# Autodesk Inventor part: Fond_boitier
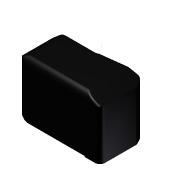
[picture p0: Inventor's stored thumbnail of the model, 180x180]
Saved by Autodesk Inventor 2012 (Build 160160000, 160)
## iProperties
Created: 2011-07
Part Number: Fond_boitier
Document SubType Name: Modeling
Designer: domi
Density: 1 g/cm^3
Material: Par défaut
Author: domi
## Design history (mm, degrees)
sketch "Esquisse1"
  geometry: L1 (-13.986, -11.692)-(16.704, -11.692) reference; L2 (18.504, -9.892)-(18.504, 4.208) reference; L3 (18.352, 4.844)-(17.078, 7.344) reference; L4 (15.831, 8.108)-(12.304, 8.108) reference; L5 (9.472, 9.948)-(7.197, 15.058) reference; L6 (6.731, 15.749)-(4.851, 17.696) reference; L7 (-10.621, 14.519)-(-16.593, 4.961) reference; L8 (16.704, -10.292)-(-13.986, -10.292) reference; L9 (-15.406, 4.219)-(-9.678, 13.386) reference; L10 (4.275, 16.278)-(5.724, 14.777) reference; L11 (5.918, 14.489)-(8.193, 9.378) reference; L12 (12.304, 6.708)-(15.831, 6.708) reference; L13 (15.831, 6.708)-(17.104, 4.208) reference; L14 (17.104, 4.208)-(17.104, -9.892) reference; L15 (16.704, -12.092)-(-13.986, -12.092); L16 (-16.932, 5.173)-(-10.891, 14.841); L17 (5.017, 18.1)-(7.018, 16.027); L18 (7.562, 15.221)-(9.838, 10.11); L19 (12.304, 8.508)-(15.831, 8.508); L20 (17.434, 7.526)-(18.708, 5.026); L21 (18.904, 4.208)-(18.904, -9.892); A1 r 1.8 centre (16.704, -9.892) between (16.704, -11.692) and (18.504, -9.892) reference; A2 r 1.4 centre (17.104, 4.208) between (18.504, 4.208) and (18.352, 4.844) reference; A3 r 1.4 centre (15.831, 6.708) between (17.078, 7.344) and (15.831, 8.108) reference; A4 r 3.1 centre (12.304, 11.208) between (9.472, 9.948) and (12.304, 8.108) reference; A5 r 2.4 centre (5.004, 14.082) between (7.197, 15.058) and (6.731, 15.749) reference; A6 r 44.4 centre (5.904, -26.692) between (4.851, 17.696) and (-10.621, 14.519) reference; A7 r 21.8 centre (1.894, -6.592) between (-16.593, 4.961) and (-19.878, -5.495) reference; A8 r 5.9 centre (-13.986, -5.792) between (-19.878, -5.495) and (-13.986, -11.692) reference; A9 r 4.5 centre (-13.986, -5.792) between (-18.48, -5.565) and (-13.986, -10.292) reference; A10 r 20.4 centre (1.894, -6.592) between (-15.406, 4.219) and (-18.48, -5.565) reference; A11 r 43 centre (5.904, -26.692) between (4.275, 16.278) and (-9.678, 13.386) reference; A12 r 1 centre (5.004, 14.082) between (5.918, 14.489) and (5.724, 14.777) reference; A13 r 4.5 centre (12.304, 11.208) between (8.193, 9.378) and (12.304, 6.708) reference; A14 r 0.4 centre (16.704, -9.892) between (16.704, -10.292) and (17.104, -9.892) reference; A15 r 6.3 centre (-13.986, -5.792) between (-20.278, -5.475) and (-13.986, -12.092); A16 r 22.2 centre (1.894, -6.592) between (-16.932, 5.173) and (-20.278, -5.475); A17 r 44.8 centre (5.904, -26.692) between (5.017, 18.1) and (-10.891, 14.841); A18 r 2.8 centre (5.004, 14.082) between (7.562, 15.221) and (7.018, 16.027); A19 r 2.7 centre (12.304, 11.208) between (9.838, 10.11) and (12.304, 8.508); A20 r 1.8 centre (15.831, 6.708) between (17.434, 7.526) and (15.831, 8.508); A21 r 1.8 centre (17.104, 4.208) between (18.904, 4.208) and (18.708, 5.026); A22 r 2.2 centre (16.704, -9.892) between (16.704, -12.092) and (18.904, -9.892); 1 further point
  constraints: 16 point on circle, 14 end point, 8 centre point, 14 other
  dimensions: "d0" = 1.8 distance between parallel lines of L8 L15
extrude "Corps" new body sketch "Esquisse1" distance "d1" = 25.5; taper "d2" = 0 deg
node "Plan de construction1"
sketch "Esquisse4"
  geometry: L1 (-16.704, -12.092)-(13.986, -12.092) reference; L2 (16.932, 5.173)-(10.891, 14.841) reference; L3 (-5.017, 18.1)-(-7.018, 16.027) reference; L4 (-7.562, 15.221)-(-9.838, 10.11) reference; L5 (-12.304, 8.508)-(-15.831, 8.508) reference; L6 (-17.434, 7.526)-(-18.708, 5.026) reference; L7 (-18.904, 4.208)-(-18.904, -9.892) reference; C1 r 1.77 at (1.596, 9.208) reference; A1 r 6.3 centre (13.986, -5.792) between (13.986, -12.092) and (20.278, -5.475) reference; A2 r 22.2 centre (-1.894, -6.592) between (20.278, -5.475) and (16.932, 5.173) reference; A3 r 44.8 centre (-5.904, -26.692) between (10.891, 14.841) and (-5.017, 18.1) reference; A4 r 2.8 centre (-5.004, 14.082) between (-7.018, 16.027) and (-7.562, 15.221) reference; A5 r 2.7 centre (-12.304, 11.208) between (-12.304, 8.508) and (-9.838, 10.11) reference; A6 r 1.8 centre (-15.831, 6.708) between (-15.831, 8.508) and (-17.434, 7.526) reference; A7 r 1.8 centre (-17.104, 4.208) between (-18.708, 5.026) and (-18.904, 4.208) reference; A8 r 2.2 centre (-16.704, -9.892) between (-18.904, -9.892) and (-16.704, -12.092) reference; 1 further point
  node "Référence2"
node "Axe de construction1"
sketch "Esquisse5"
  geometry: L1 (13.986, -12.092)-(-16.704, -12.092) reference; L2 (-18.904, -9.892)-(-18.904, 4.208) reference; L3 (-18.708, 5.026)-(-17.434, 7.526) reference; L4 (-15.831, 8.508)-(-12.304, 8.508) reference; L5 (-9.838, 10.11)-(-7.562, 15.221) reference; L6 (-7.018, 16.027)-(-5.017, 18.1) reference; L7 (10.891, 14.841)-(16.932, 5.173) reference; L8 (16.473, 5.908)-(1.596, 5.908); L9 (-12.304, 8.508)-(-2.132, 7.614); A1 r 6.3 centre (13.986, -5.792) between (13.986, -12.092) and (20.278, -5.475) reference; A2 r 2.2 centre (-16.704, -9.892) between (-18.904, -9.892) and (-16.704, -12.092) reference; A3 r 1.8 centre (-17.104, 4.208) between (-18.708, 5.026) and (-18.904, 4.208) reference; A4 r 1.8 centre (-15.831, 6.708) between (-15.831, 8.508) and (-17.434, 7.526) reference; A5 r 2.7 centre (-12.304, 11.208) between (-12.304, 8.508) and (-9.838, 10.11) reference; A6 r 2.8 centre (-5.004, 14.082) between (-7.018, 16.027) and (-7.562, 15.221) reference; A7 r 44.8 centre (-5.904, -26.692) between (10.891, 14.841) and (-5.017, 18.1) reference; A8 r 22.2 centre (-1.894, -6.592) between (20.278, -5.475) and (16.932, 5.173) reference; A9 r 3.3 centre (1.596, 9.208) between (-0.834, 6.975) and (1.596, 5.908); A10 r 2 centre (-2.307, 5.622) between (-0.834, 6.975) and (-2.132, 7.614); 2 further points
  constraints: 4 end point, 4 point on circle, 3 tangent, 2 centre point, 1 coincident, 1 parallel, 1 point on line
  dimensions: "d10" = 6.6 diameter of A9; "d108" = 2 radius of A10
extrude "Complement corps" cut sketch "Esquisse5" stored distance "d11" = 1.8; taper "d12" = 0 deg
sketch "Esquisse6"
  geometry: L1 (0, 0)-(0, 25.5) reference; L2 (30.69, 0)-(0, 0) reference; L3 (30.69, 0)-(30.69, 25.5) reference; L4 (32.89, 0)-(32.89, 25.5) reference; L5 (32.89, 22.5)-(25.89, 25.5); L6 (25.89, 25.5)-(32.89, 25.5); L7 (32.89, 25.5)-(32.89, 22.5); L8 (30.69, 25.5)-(0, 25.5) reference; 1 further point
  constraints: 6 end point, 1 collinear, 1 perpendicular, 1 point on line
  dimensions: "d14" = 3 distance of L4.end L5.start; "d15" = 7 distance of L5.end L4.end
extrude "Chanfrein 1" cut sketch "Esquisse6" stored distance "d16" = 1.8; taper "d17" = 0 deg
sketch "Esquisse7"
  geometry: L1 (0, 0)-(-22.5, 0) reference; L2 (0, 14.1)-(0, 0) reference; L3 (0, 14.1)-(-22.5, 14.1) reference; L4 (0, -2.2)-(-25.5, -2.2) reference; L5 (0, -2.2)-(-23.443, -2.2) reference; L6 (-25.6, 18.329)-(-25.6, 16.6) reference; L7 (-25.6, 16.6)-(-25.6, 14.6) reference; L8 (-25.6, 4.417)-(-25.6, 14.6) reference; L9 (-25.6, -2.2)-(-25.6, 4.417) reference; L10 (-22.6, 0.8)-(-25.6, 0.8); L11 (-22.6, 0.8)-(-22.6, -2.2); L12 (-22.6, -2.2)-(-25.6, -2.2); L13 (-25.6, -2.2)-(-25.6, 0.8); L14 (-25.6, -2.2)-(-25.6, 18.329) reference; L15 (-23.443, -2.2)-(-25.5, -2.2) reference; L16 (-22.5, 14.1)-(-22.5, 0) reference; A1 r 3 centre (-22.6, 0.8) between (-25.6, 0.8) and (-22.6, -2.2); 1 further point
  constraints: 8 end point, 4 tangent, 2 perpendicular, 2 point on circle, 2 point on line, 1 centre point, 1 collinear
  dimensions: "d18" = 6 diameter of A1
extrude "Arrondi1" cut sketch "Esquisse7" stored distance "d19" = 1.8; taper "d20" = 0 deg
fillet "Congé1" dims "d53" = 1
node "Plan de construction chanfrein 2"
  node "Axe de construction2"
sketch "Esquisse8"
  geometry: L1 (11.1, -11.807)-(11.1, -8.084); L2 (11.1, -11.807)-(11.1, -17.224); L3 (0, 15.601)-(0, -2) reference; L4 (-11, -2)-(-11, -12.287) reference; L5 (-11, -12.287)-(-25.5, -12.287) reference; L6 (-25.5, -12.287)-(-25.5, 17.851) reference; L7 (-25.5, 17.851)-(-2.9, 17.851) reference; L8 (-6, -2)-(0, -1); L9 (-8.744, -2.457)-(0, -2.457); L10 (0, -2)-(0, -2.457); L11 (-6, -2)-(-8.744, -2.457); L12 (0, -2)-(-11, -2) reference; 3 further points; 1 other entity
  constraints: 12 end point, 1 collinear, 1 parallel, 1 perpendicular, 1 point on line, 1 other
  dimensions: "d109" = 6 distance from line of L3 L8.start; "d112" = 1.45727 distance from line of L8.end L9
extrude "Chanfein2" cut sketch "Esquisse8" stored distance "d24" = 1.8; taper "d25" = 0 deg
sketch "Esquisse9"
  geometry: L1 (0, -1)-(0, -2) reference; L2 (0, -2)-(-6, -2) reference; L3 (0, -1)-(-6, -2) reference; L4 (0, 15.601)-(0, -1) reference; L5 (-11, -2)-(-11, -12.287) reference; L6 (-6, -2)-(-11, -2) reference; L7 (-25.5, 17.851)-(-2.9, 17.851) reference; L8 (-25.5, -12.287)-(-25.5, 17.851) reference; L9 (-11, -12.287)-(-25.5, -12.287) reference; 3 further points; 1 other entity
  constraints: 1 other
extrude "Suite chanfrein2" cut sketch "Esquisse9" distance "d26" = 3.904; taper "d27" = 0 deg
sketch "Esquisse10"
  geometry: L1 (-3.813, 14.5)-(-3.813, -11) reference; L2 (0, -11)-(-3.813, -11); A1 r 6 centre (2.187, -5) between (-3.813, -5) and (2.187, -11); 9 further points; 1 other entity
  constraints: 2 end point, 2 point on circle, 2 point on line, 2 tangent, 1 centre point, 1 perpendicular, 2 other
  dimensions: "d107" = 6 distance from line of L2 A1.start
extrude "Arrondi2" cut sketch "Esquisse10" stored distance "d30" = 3.904; taper "d31" = 0 deg
sketch "Esquisse2"
  geometry: L1 (-16.704, -12.092)-(13.986, -12.092) reference; L2 (16.932, 5.173)-(10.891, 14.841) reference; L3 (-16.704, -11.692)-(13.986, -11.692); L4 (16.593, 4.961)-(10.621, 14.519); L5 (-4.851, 17.696)-(-6.731, 15.749); L6 (-7.197, 15.058)-(-9.472, 9.948); L7 (-12.304, 8.108)-(-15.831, 8.108); L8 (-17.078, 7.344)-(-18.352, 4.844); L9 (-18.504, 4.208)-(-18.504, -9.892); L10 (-5.017, 18.1)-(-7.018, 16.027) reference; L11 (-7.562, 15.221)-(-9.838, 10.11) reference; L12 (-12.304, 8.508)-(-15.831, 8.508) reference; L13 (-17.434, 7.526)-(-18.708, 5.026) reference; L14 (-18.904, 4.208)-(-18.904, -9.892) reference; A1 r 6.3 centre (13.986, -5.792) between (13.986, -12.092) and (20.278, -5.475) reference; A2 r 22.2 centre (-1.894, -6.592) between (20.278, -5.475) and (16.932, 5.173) reference; A3 r 44.8 centre (-5.904, -26.692) between (10.891, 14.841) and (-5.017, 18.1) reference; A4 r 2.2 centre (-16.704, -9.892) between (-18.904, -9.892) and (-16.704, -12.092) reference; A5 r 5.9 centre (13.986, -5.792) between (13.986, -11.692) and (19.878, -5.495); A6 r 21.8 centre (-1.894, -6.592) between (19.878, -5.495) and (16.593, 4.961); A7 r 44.4 centre (-5.904, -26.692) between (10.621, 14.519) and (-4.851, 17.696); A8 r 2.4 centre (-5.004, 14.082) between (-6.731, 15.749) and (-7.197, 15.058); A9 r 3.1 centre (-12.304, 11.208) between (-12.304, 8.108) and (-9.472, 9.948); A10 r 1.4 centre (-15.831, 6.708) between (-15.831, 8.108) and (-17.078, 7.344); A11 r 1.4 centre (-17.104, 4.208) between (-18.352, 4.844) and (-18.504, 4.208); A12 r 1.8 centre (-16.704, -9.892) between (-18.504, -9.892) and (-16.704, -11.692); A13 r 2.8 centre (-5.004, 14.082) between (-7.018, 16.027) and (-7.562, 15.221) reference; A14 r 2.7 centre (-12.304, 11.208) between (-12.304, 8.508) and (-9.838, 10.11) reference; A15 r 1.8 centre (-15.831, 6.708) between (-15.831, 8.508) and (-17.434, 7.526) reference; A16 r 1.8 centre (-17.104, 4.208) between (-18.708, 5.026) and (-18.904, 4.208) reference; 1 further point
  constraints: 16 point on circle, 14 end point, 8 centre point, 4 other
extrude "Epaulement Languette" cut sketch "Esquisse2" distance "d4" = 1; taper "d5" = 0 deg
sketch "Esquisse15"
  geometry: L1 (-16.704, -11.692)-(13.986, -11.692) reference; L2 (13.986, -12.092)-(-16.704, -12.092) reference; L3 (-18.504, 4.208)-(-18.504, -9.892) reference; L4 (-18.904, -9.892)-(-18.904, 4.208) reference; L5 (-17.078, 7.344)-(-18.352, 4.844) reference; L6 (-18.708, 5.026)-(-17.434, 7.526) reference; L7 (-12.304, 8.108)-(-15.831, 8.108) reference; L8 (-15.831, 8.508)-(-12.304, 8.508) reference; L9 (-11.904, -12.092)-(-11.904, -11.692); L10 (-11.904, -11.692)-(-16.704, -11.692); L11 (-11.904, -12.092)-(-16.704, -12.092); L12 (-9.838, 10.11)-(-7.562, 15.221) reference; L13 (-7.197, 15.058)-(-9.472, 9.948) reference; L14 (-9.158, 10.653)-(-9.247, 10.693); L15 (-9.247, 10.693)-(-9.523, 10.816); L16 (-9.158, 10.653)-(-9.472, 9.948); L17 (-9.523, 10.816)-(-9.838, 10.11); A1 r 1.8 centre (-16.704, -9.892) between (-18.504, -9.892) and (-16.704, -11.692) reference; A2 r 2.2 centre (-16.704, -9.892) between (-18.904, -9.892) and (-16.704, -12.092) reference; A3 r 1.4 centre (-17.104, 4.208) between (-18.352, 4.844) and (-18.504, 4.208) reference; A4 r 1.8 centre (-17.104, 4.208) between (-18.708, 5.026) and (-18.904, 4.208) reference; A5 r 1.8 centre (-15.831, 6.708) between (-15.831, 8.508) and (-17.434, 7.526) reference; A6 r 1.4 centre (-15.831, 6.708) between (-15.831, 8.108) and (-17.078, 7.344) reference; A7 r 2.7 centre (-12.304, 11.208) between (-12.304, 8.508) and (-9.838, 10.11) reference; A8 r 3.1 centre (-12.304, 11.208) between (-12.304, 8.108) and (-9.472, 9.948) reference; 3 further points
  constraints: 14 end point, 4 point on line, 3 collinear, 3 perpendicular, 3 tangent, 1 point on circle
  dimensions: "d49" = 7 distance between parallel lines of L4 L9; "d50" = 22.7848 distance from line of L2 L14.end
extrude "Non languette" join sketch "Esquisse15" distance "d51" = 1 (= d4); taper "d52" = 0 deg
sketch "Esquisse11"
  geometry: C1 r 5.1 at (0, 5.1); 2 further points
  constraints: 1 centre point, 1 coincident
  dimensions: "d33" = 10.2 diameter of C1
extrude "Bossage inter_1" join sketch "Esquisse11" distance "d34" = 2.35; taper "d35" = 0 deg
sketch "Esquisse12"
  geometry: C1 r 3.75 at (-1.596, 9.208); 2 further points
  constraints: 1 centre point, 1 coincident
  dimensions: "d36" = 7.5 diameter of C1
extrude "Bossage exter_1" join sketch "Esquisse12" distance "d37" = 1; taper "d38" = 0 deg
sketch "Esquisse13"
  geometry: C1 r 3.75 at (0, 0); 2 further points
  constraints: 1 centre point, 1 coincident
  dimensions: "d39" = 7.5 diameter of C1
extrude "Trou lamé inter_1" cut sketch "Esquisse13" distance "d40" = 1.85; taper "d41" = 0 deg
sketch "Esquisse14"
  geometry: 2 further points
hole "Trou lamé exter_1" sketch "Esquisse14" at (0, 0) diameter "d42" = 4.5; stored, may be unused: countersink angle "d46" = 90 deg, drill point angle "d48" = 118 deg; dims "d43" = 6, "d44" = 6.5, "d45" = 1, "d47" = 8
node "Plan Nervure1"
sketch "Esquisse16"
  geometry: L1 (8.509, 0)-(6.709, 0) reference; L2 (-12.092, 0)-(-12.092, 22.6) reference; L3 (-6.092, 23.494)-(-6.092, 13.394); L4 (1.408, 23.494)-(1.408, 19.7); L5 (8.509, 14.5)-(8.509, 0) reference; L6 (8.504, 21.717)-(8.504, 14.5) reference; L7 (7.893, 25.352)-(8.504, 21.717) reference; L8 (-9.892, 25.352)-(7.893, 25.352) reference; L9 (8.504, 14.5)-(8.509, 14.5) reference; L10 (6.709, 0)-(6.709, 12.7) reference; L11 (6.709, 12.7)-(6.697, 12.7) reference; L12 (6.697, 12.7)-(6.697, 21.527) reference; L13 (6.697, 21.527)-(6.383, 23.394) reference; L14 (6.383, 23.394)-(-9.992, 23.394) reference; L15 (-10.292, 22.6)-(-10.292, 0) reference; L16 (-10.292, 0)-(-12.092, 0) reference; A1 r 3 centre (-9.092, 22.6) between (-10.756, 25.096) and (-12.092, 22.6) reference; A2 r 1.2 centre (-9.092, 22.6) between (-9.992, 23.394) and (-10.292, 22.6) reference; 1 further point
  constraints: 4 end point, 1 parallel, 1 other
  dimensions: "d60" = 19.7 distance from line of L1 L4.end; "d61" = 6 distance between parallel lines of L2 L3; "d62" = 7.5 distance between parallel lines of L3 L4; "d92" = 10.1 distance of L3.start L3.end
feature "Nervure1" sketch "Esquisse16" dims "d63" = 1, "d64" = 1, "d65" = 0
node "Plan Nervure 2"
sketch "Esquisse17"
  geometry: L1 (0.123, 21.379)-(0.123, 2); L2 (2.229, 0)-(-10.337, 0); L3 (-2.877, 21.379)-(-2.877, 2); L4 (0.123, 2)-(-2.877, 2); L5 (0.123, 2)-(0.123, 0); L6 (-2.877, 2)-(-2.877, 0); L7 (-9.68, 0)-(-11.24, 0) reference; L8 (-11.24, 0)-(-11.24, 1) reference; L9 (-11.24, 1)-(-11.671, 1) reference; L10 (-11.671, 1)-(-11.671, 24.133) reference; L11 (5.908, 25.169)-(5.908, 14.5) reference; L12 (5.908, 14.5)-(6.265, 14.5) reference; L13 (6.265, 14.5)-(6.265, 1) reference; L14 (6.265, 1)-(5.51, 1) reference; L15 (5.51, 1)-(5.51, 0) reference; L16 (-10.64, 25.169)-(5.908, 25.169) reference; L17 (2.733, 0)-(2.733, 23.212) reference; L18 (2.733, 23.212)-(-9.68, 23.212) reference; L19 (-9.68, 23.212)-(-9.68, 0) reference; L20 (5.51, 0)-(2.733, 0) reference; A1 r 3 centre (-9.092, 22.6) between (-10.64, 25.169) and (-11.671, 24.133) reference; 1 further point
  constraints: 12 end point, 6 perpendicular, 2 point on line
  dimensions: "d67" = 3 distance between parallel lines of L3 L1; "d72" = 2 distance between parallel lines of L2 L4
feature "Nervure2" sketch "Esquisse17" dims "d69" = 1, "d70" = 1, "d71" = 0
sketch "Esquisse18"
  geometry: C1 r 2.25 at (0, 0) reference; C2 r 3.75 at (0, 0) reference; C3 r 3.4 at (0, 0)
  constraints: 1 centre point, 1 coincident
  dimensions: "d89" = 6.8 diameter of C3
extrude "logement joint" cut sketch "Esquisse18" distance "d90" = 1.8; taper "d91" = 0 deg
sketch "Esquisse19"
  geometry: L1 (11.641, 13.018)-(11.641, 0.808) reference; L2 (0.441, 9.048)-(0.441, 3.24) reference; L3 (0.441, 13.768)-(0.441, 9.048) reference; L4 (0.441, 3.24)-(0.441, 0.858) reference; L5 (0.441, 0.858)-(11.641, 0.858) reference; L6 (5.441, 13.768)-(10.077, 13.768) reference; L7 (0.241, 11.018)-(11.841, 11.018); L8 (11.841, 11.018)-(11.841, 1.018); L9 (11.841, 1.018)-(0.241, 1.018); L10 (0.241, 1.018)-(0.241, 11.018); L11 (-2.654, 6.018)-(14.204, 6.018); L12 (11.641, 13.018)-(1.641, 13.018) reference; 1 further point
  constraints: 24 end point, 4 horizontal, 4 vertical, 2 parallel, 2 perpendicular, 13 other
  dimensions: "d117" = 10 distance between parallel lines of L9 L7; "d120" = 0.2 distance between parallel lines of L3 L10; "d121" = 0.2 distance between parallel lines of L8 L1 (derived); "d122" = 12.1595 distance between parallel lines of L5 L12 (derived); "d123" = 14 diameter of L12 L11
extrude "évidemment pour cage moteur" cut sketch "Esquisse19" distance "d118" = 0.3; taper "d119" = 0 deg
node "Solide1"
node "Corps solides"
node "Corps surfaciques"
feature "Coque" dims "d32" = 1.8
node "Référence1"
node "Boucle projetée1"
node "Boucle projetée3"
node "Boucle projetée4"
node "Boucle projetée5"
node "Boucle projetée6"
node "Projeter les arêtes coupées1"
node "Projeter les arêtes coupées2"
node "Projeter les arêtes coupées4"
node "Projeter les arêtes coupées5"
node "Projeter les arêtes coupées6"
other parameters: "d8" = -14.5, "d58" = 12.25, "d66" = -16.25, "d100" = 1.23918
